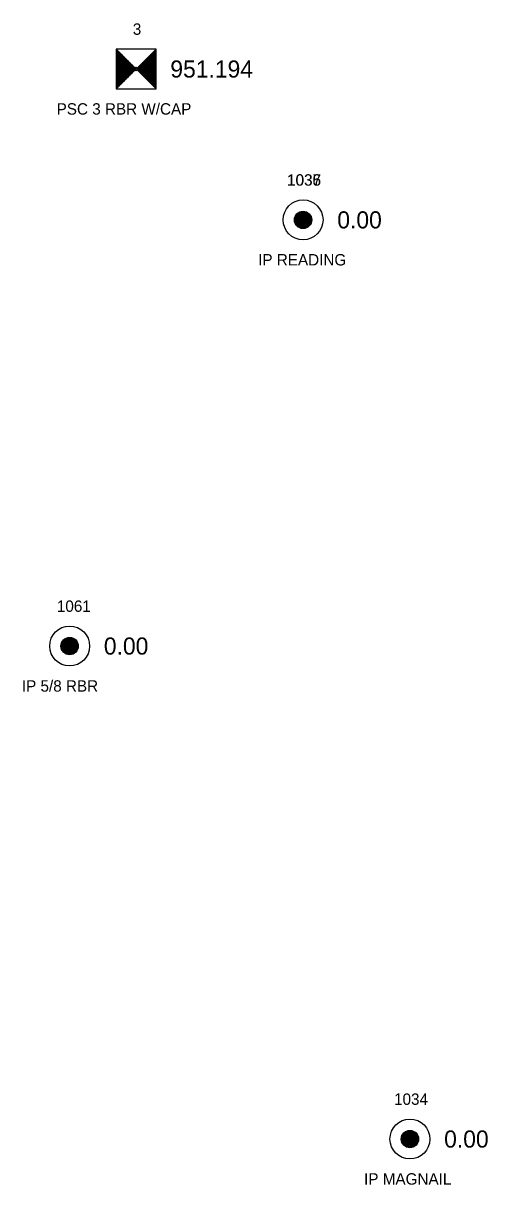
# Model space of a CAD drawing. Extents: x 1528109 to 1531398, y 1157799 to 1162548.
# Drawn here: x 1529035.6 to 1529076.3, y 1162446.1 to 1162548 of the extents above; entities that cross this region are included whole.
import ezdxf

# ---------------------------------------------------------------- set-up
doc = ezdxf.new("R2010")
doc.units = 0
for name, color, linetype in [('RD_EX_DV_Prop_txCode', 7, 'Continuous'), ('RD_EX_DV_PropPin', 7, 'Continuous'), ('RD_EX_TX_DV_Prop_ELEV', 7, 'Continuous'), ('RD_HC_Survey', 7, 'Continuous'), ('RD_HC_Survey_ELEV', 7, 'Continuous'), ('RD_HC_txCode', 7, 'Continuous'), ('RD_SMD_Locator', 7, 'Continuous')]:
    doc.layers.add(name, color=color, linetype=linetype)

msp = doc.modelspace()

# ---------------------------------------------------------------- linework, layer by layer
at = {"layer": 'RD_EX_DV_PropPin'}
for p, q in [((1529059.6, 1162530.18), (1529059.6, 1162531.28)), ((1529059.6, 1162530.18), (1529059.6, 1162531.28)), ((1529059.6, 1162530.18), (1529059.6, 1162531.28)), ((1529059.64, 1162530.14), (1529059.64, 1162531.31)), ((1529059.64, 1162530.14), (1529059.64, 1162531.31)), ((1529059.64, 1162530.14), (1529059.64, 1162531.31)), ((1529059.67, 1162530.12), (1529059.67, 1162531.34)), ((1529059.67, 1162530.12), (1529059.67, 1162531.34)), ((1529059.67, 1162530.12), (1529059.67, 1162531.34)), ((1529059.71, 1162530.09), (1529059.71, 1162531.36)), ((1529059.71, 1162530.09), (1529059.71, 1162531.36)), ((1529059.71, 1162530.09), (1529059.71, 1162531.36)), ((1529059.74, 1162530.07), (1529059.74, 1162531.38)), ((1529059.74, 1162530.07), (1529059.74, 1162531.38)), ((1529059.74, 1162530.07), (1529059.74, 1162531.38)), ((1529059.78, 1162530.05), (1529059.78, 1162531.4)), ((1529059.78, 1162530.05), (1529059.78, 1162531.4)), ((1529059.78, 1162530.05), (1529059.78, 1162531.4)), ((1529059.81, 1162530.03), (1529059.81, 1162531.42)), ((1529059.81, 1162530.03), (1529059.81, 1162531.42)), ((1529059.81, 1162530.03), (1529059.81, 1162531.42)), ((1529059.85, 1162530.02), (1529059.85, 1162531.43)), ((1529059.85, 1162530.02), (1529059.85, 1162531.43)), ((1529059.85, 1162530.02), (1529059.85, 1162531.43)), ((1529059.88, 1162530.01), (1529059.88, 1162531.45)), ((1529059.88, 1162530.01), (1529059.88, 1162531.45)), ((1529059.88, 1162530.01), (1529059.88, 1162531.45)), ((1529059.92, 1162529.99), (1529059.92, 1162531.46)), ((1529059.92, 1162529.99), (1529059.92, 1162531.46)), ((1529059.92, 1162529.99), (1529059.92, 1162531.46)), ((1529059.95, 1162529.99), (1529059.95, 1162531.47)), ((1529059.95, 1162529.99), (1529059.95, 1162531.47)), ((1529059.95, 1162529.99), (1529059.95, 1162531.47)), ((1529059.99, 1162529.98), (1529059.99, 1162531.47)), ((1529059.99, 1162529.98), (1529059.99, 1162531.47)), ((1529059.99, 1162529.98), (1529059.99, 1162531.47)), ((1529060.02, 1162529.97), (1529060.02, 1162531.48)), ((1529060.02, 1162529.97), (1529060.02, 1162531.48)), ((1529060.02, 1162529.97), (1529060.02, 1162531.48)), ((1529060.06, 1162529.97), (1529060.06, 1162531.48)), ((1529060.06, 1162529.97), (1529060.06, 1162531.48)), ((1529060.06, 1162529.97), (1529060.06, 1162531.48)), ((1529060.09, 1162529.97), (1529060.09, 1162531.49)), ((1529060.09, 1162529.97), (1529060.09, 1162531.49)), ((1529060.09, 1162529.97), (1529060.09, 1162531.49)), ((1529060.13, 1162529.97), (1529060.13, 1162531.49)), ((1529060.13, 1162529.97), (1529060.13, 1162531.49)), ((1529060.13, 1162529.97), (1529060.13, 1162531.49)), ((1529060.16, 1162529.97), (1529060.16, 1162531.49)), ((1529060.16, 1162529.97), (1529060.16, 1162531.49)), ((1529060.16, 1162529.97), (1529060.16, 1162531.49)), ((1529060.2, 1162529.97), (1529060.2, 1162531.48)), ((1529060.2, 1162529.97), (1529060.2, 1162531.48)), ((1529060.2, 1162529.97), (1529060.2, 1162531.48)), ((1529060.23, 1162529.97), (1529060.23, 1162531.48)), ((1529060.23, 1162529.97), (1529060.23, 1162531.48)), ((1529060.23, 1162529.97), (1529060.23, 1162531.48)), ((1529060.27, 1162529.98), (1529060.27, 1162531.47)), ((1529060.27, 1162529.98), (1529060.27, 1162531.47)), ((1529060.27, 1162529.98), (1529060.27, 1162531.47)), ((1529060.3, 1162529.99), (1529060.3, 1162531.47)), ((1529060.3, 1162529.99), (1529060.3, 1162531.47)), ((1529060.3, 1162529.99), (1529060.3, 1162531.47)), ((1529060.34, 1162529.99), (1529060.34, 1162531.46)), ((1529060.34, 1162529.99), (1529060.34, 1162531.46)), ((1529060.34, 1162529.99), (1529060.34, 1162531.46)), ((1529060.37, 1162530.01), (1529060.37, 1162531.45)), ((1529060.37, 1162530.01), (1529060.37, 1162531.45)), ((1529060.37, 1162530.01), (1529060.37, 1162531.45)), ((1529060.41, 1162530.02), (1529060.41, 1162531.43)), ((1529060.41, 1162530.02), (1529060.41, 1162531.43)), ((1529060.41, 1162530.02), (1529060.41, 1162531.43)), ((1529060.44, 1162530.03), (1529060.44, 1162531.42)), ((1529060.44, 1162530.03), (1529060.44, 1162531.42)), ((1529060.44, 1162530.03), (1529060.44, 1162531.42)), ((1529060.48, 1162530.05), (1529060.48, 1162531.4)), ((1529060.48, 1162530.05), (1529060.48, 1162531.4)), ((1529060.48, 1162530.05), (1529060.48, 1162531.4)), ((1529060.51, 1162530.07), (1529060.51, 1162531.38)), ((1529060.51, 1162530.07), (1529060.51, 1162531.38)), ((1529060.51, 1162530.07), (1529060.51, 1162531.38)), ((1529060.55, 1162530.09), (1529060.55, 1162531.36)), ((1529060.55, 1162530.09), (1529060.55, 1162531.36)), ((1529060.55, 1162530.09), (1529060.55, 1162531.36)), ((1529060.58, 1162530.12), (1529060.58, 1162531.34)), ((1529060.58, 1162530.12), (1529060.58, 1162531.34)), ((1529060.58, 1162530.12), (1529060.58, 1162531.34)), ((1529060.62, 1162530.14), (1529060.62, 1162531.31)), ((1529060.62, 1162530.14), (1529060.62, 1162531.31)), ((1529060.62, 1162530.14), (1529060.62, 1162531.31)), ((1529060.65, 1162530.18), (1529060.65, 1162531.28)), ((1529060.65, 1162530.18), (1529060.65, 1162531.28)), ((1529060.65, 1162530.18), (1529060.65, 1162531.28)), ((1529059.39, 1162530.53), (1529059.39, 1162530.92)), ((1529059.39, 1162530.53), (1529059.39, 1162530.92)), ((1529059.39, 1162530.53), (1529059.39, 1162530.92)), ((1529059.43, 1162530.43), (1529059.43, 1162531.02)), ((1529059.43, 1162530.43), (1529059.43, 1162531.02)), ((1529059.43, 1162530.43), (1529059.43, 1162531.02)), ((1529059.46, 1162530.36), (1529059.46, 1162531.1)), ((1529059.46, 1162530.36), (1529059.46, 1162531.1)), ((1529059.46, 1162530.36), (1529059.46, 1162531.1)), ((1529059.5, 1162530.3), (1529059.5, 1162531.15)), ((1529059.5, 1162530.3), (1529059.5, 1162531.15)), ((1529059.5, 1162530.3), (1529059.5, 1162531.15)), ((1529059.53, 1162530.25), (1529059.53, 1162531.2)), ((1529059.53, 1162530.25), (1529059.53, 1162531.2)), ((1529059.53, 1162530.25), (1529059.53, 1162531.2)), ((1529059.57, 1162530.21), (1529059.57, 1162531.24)), ((1529059.57, 1162530.21), (1529059.57, 1162531.24)), ((1529059.57, 1162530.21), (1529059.57, 1162531.24)), ((1529060.69, 1162530.21), (1529060.69, 1162531.24)), ((1529060.69, 1162530.21), (1529060.69, 1162531.24)), ((1529060.69, 1162530.21), (1529060.69, 1162531.24)), ((1529060.72, 1162530.25), (1529060.72, 1162531.2)), ((1529060.72, 1162530.25), (1529060.72, 1162531.2)), ((1529060.72, 1162530.25), (1529060.72, 1162531.2)), ((1529060.76, 1162530.3), (1529060.76, 1162531.15)), ((1529060.76, 1162530.3), (1529060.76, 1162531.15)), ((1529060.76, 1162530.3), (1529060.76, 1162531.15)), ((1529060.79, 1162530.36), (1529060.79, 1162531.1)), ((1529060.79, 1162530.36), (1529060.79, 1162531.1)), ((1529060.79, 1162530.36), (1529060.79, 1162531.1)), ((1529060.83, 1162530.43), (1529060.83, 1162531.02)), ((1529060.83, 1162530.43), (1529060.83, 1162531.02)), ((1529060.83, 1162530.43), (1529060.83, 1162531.02)), ((1529060.86, 1162530.53), (1529060.86, 1162530.92)), ((1529060.86, 1162530.53), (1529060.86, 1162530.92)), ((1529060.86, 1162530.53), (1529060.86, 1162530.92)), ((1529038.96, 1162493.05), (1529038.96, 1162493.65)), ((1529039, 1162492.98), (1529039, 1162493.72)), ((1529039.03, 1162492.93), (1529039.03, 1162493.78)), ((1529039.07, 1162492.88), (1529039.07, 1162493.83)), ((1529039.1, 1162492.84), (1529039.1, 1162493.87)), ((1529039.14, 1162492.8), (1529039.14, 1162493.9)), ((1529039.17, 1162492.77), (1529039.17, 1162493.93)), ((1529039.21, 1162492.74), (1529039.21, 1162493.96)), ((1529039.24, 1162492.72), (1529039.24, 1162493.99)), ((1529039.28, 1162492.7), (1529039.28, 1162494.01)), ((1529039.31, 1162492.68), (1529039.31, 1162494.03)), ((1529039.35, 1162492.66), (1529039.35, 1162494.05)), ((1529039.38, 1162492.65), (1529039.38, 1162494.06)), ((1529039.42, 1162492.63), (1529039.42, 1162494.07)), ((1529039.45, 1162492.62), (1529039.45, 1162494.08)), ((1529039.49, 1162492.61), (1529039.49, 1162494.09)), ((1529039.52, 1162492.6), (1529039.52, 1162494.1)), ((1529039.56, 1162492.6), (1529039.56, 1162494.11)), ((1529039.59, 1162492.59), (1529039.59, 1162494.11)), ((1529039.63, 1162492.59), (1529039.63, 1162494.11)), ((1529039.66, 1162492.59), (1529039.66, 1162494.11)), ((1529039.7, 1162492.59), (1529039.7, 1162494.11)), ((1529039.73, 1162492.59), (1529039.73, 1162494.11)), ((1529039.77, 1162492.6), (1529039.77, 1162494.11)), ((1529039.8, 1162492.6), (1529039.8, 1162494.1)), ((1529039.84, 1162492.61), (1529039.84, 1162494.09)), ((1529039.87, 1162492.62), (1529039.87, 1162494.08)), ((1529039.91, 1162492.63), (1529039.91, 1162494.07)), ((1529039.94, 1162492.65), (1529039.94, 1162494.06)), ((1529039.98, 1162492.66), (1529039.98, 1162494.05)), ((1529040.01, 1162492.68), (1529040.01, 1162494.03)), ((1529040.05, 1162492.7), (1529040.05, 1162494.01)), ((1529040.08, 1162492.72), (1529040.08, 1162493.99)), ((1529040.12, 1162492.74), (1529040.12, 1162493.96)), ((1529040.15, 1162492.77), (1529040.15, 1162493.93)), ((1529040.19, 1162492.8), (1529040.19, 1162493.9)), ((1529040.22, 1162492.84), (1529040.22, 1162493.87)), ((1529040.26, 1162492.88), (1529040.26, 1162493.83)), ((1529040.29, 1162492.93), (1529040.29, 1162493.78)), ((1529040.33, 1162492.98), (1529040.33, 1162493.72)), ((1529040.36, 1162493.05), (1529040.36, 1162493.65)), ((1529038.93, 1162493.16), (1529038.93, 1162493.55)), ((1529040.4, 1162493.16), (1529040.4, 1162493.55)), ((1529069.15, 1162449.44), (1529069.15, 1162450.79)), ((1529069.18, 1162449.42), (1529069.18, 1162450.81)), ((1529069.22, 1162449.41), (1529069.22, 1162450.82)), ((1529069.25, 1162449.39), (1529069.25, 1162450.83)), ((1529069.29, 1162449.38), (1529069.29, 1162450.84)), ((1529069.32, 1162449.37), (1529069.32, 1162450.85)), ((1529069.36, 1162449.37), (1529069.36, 1162450.86)), ((1529069.39, 1162449.36), (1529069.39, 1162450.87)), ((1529069.43, 1162449.36), (1529069.43, 1162450.87)), ((1529069.46, 1162449.35), (1529069.46, 1162450.87)), ((1529069.5, 1162449.35), (1529069.5, 1162450.87)), ((1529069.53, 1162449.35), (1529069.53, 1162450.87)), ((1529069.57, 1162449.36), (1529069.57, 1162450.87)), ((1529069.61, 1162449.36), (1529069.61, 1162450.87)), ((1529069.64, 1162449.37), (1529069.64, 1162450.86)), ((1529069.68, 1162449.37), (1529069.68, 1162450.85)), ((1529069.71, 1162449.38), (1529069.71, 1162450.84)), ((1529069.75, 1162449.39), (1529069.75, 1162450.83)), ((1529069.78, 1162449.41), (1529069.78, 1162450.82)), ((1529069.82, 1162449.42), (1529069.82, 1162450.81)), ((1529069.85, 1162449.44), (1529069.85, 1162450.79)), ((1529068.76, 1162449.92), (1529068.76, 1162450.31)), ((1529068.8, 1162449.82), (1529068.8, 1162450.41)), ((1529068.83, 1162449.74), (1529068.83, 1162450.48)), ((1529068.87, 1162449.69), (1529068.87, 1162450.54)), ((1529068.9, 1162449.64), (1529068.9, 1162450.59)), ((1529068.94, 1162449.6), (1529068.94, 1162450.63)), ((1529068.97, 1162449.56), (1529068.97, 1162450.66)), ((1529069.01, 1162449.53), (1529069.01, 1162450.7)), ((1529069.04, 1162449.5), (1529069.04, 1162450.72)), ((1529069.08, 1162449.48), (1529069.08, 1162450.75)), ((1529069.11, 1162449.46), (1529069.11, 1162450.77)), ((1529069.89, 1162449.46), (1529069.89, 1162450.77)), ((1529069.92, 1162449.48), (1529069.92, 1162450.75)), ((1529069.96, 1162449.5), (1529069.96, 1162450.72)), ((1529069.99, 1162449.53), (1529069.99, 1162450.7)), ((1529070.03, 1162449.56), (1529070.03, 1162450.66)), ((1529070.06, 1162449.6), (1529070.06, 1162450.63)), ((1529070.1, 1162449.64), (1529070.1, 1162450.59)), ((1529070.13, 1162449.69), (1529070.13, 1162450.54)), ((1529070.17, 1162449.74), (1529070.17, 1162450.48)), ((1529070.2, 1162449.82), (1529070.2, 1162450.41)), ((1529070.24, 1162449.92), (1529070.24, 1162450.31))]:
    msp.add_line(p, q, dxfattribs=at)
for centre, radius in [((1529060.13, 1162530.73), 1.75), ((1529060.13, 1162530.73), 1.75), ((1529060.13, 1162530.73), 1.75), ((1529060.13, 1162530.73), 0.761), ((1529060.13, 1162530.73), 0.761), ((1529060.13, 1162530.73), 0.761), ((1529039.66, 1162493.35), 1.75), ((1529039.66, 1162493.35), 0.761), ((1529069.5, 1162450.11), 1.75), ((1529069.5, 1162450.11), 0.761)]:
    msp.add_circle(centre, radius, dxfattribs=at)
at = {"layer": 'RD_HC_Survey'}
for p, q in [((1529043.74, 1162545.71), (1529047.24, 1162542.21)), ((1529047.24, 1162545.71), (1529043.74, 1162542.21)), ((1529043.76, 1162545.69), (1529043.76, 1162542.24)), ((1529043.79, 1162545.66), (1529043.79, 1162542.26)), ((1529043.81, 1162545.64), (1529043.81, 1162542.29)), ((1529043.84, 1162545.61), (1529043.84, 1162542.31)), ((1529043.86, 1162545.59), (1529043.86, 1162542.34)), ((1529043.88, 1162545.56), (1529043.88, 1162542.36)), ((1529043.91, 1162545.54), (1529043.91, 1162542.38)), ((1529047.06, 1162545.54), (1529047.06, 1162542.38)), ((1529047.09, 1162545.56), (1529047.09, 1162542.36)), ((1529047.11, 1162545.59), (1529047.11, 1162542.34)), ((1529047.14, 1162545.61), (1529047.14, 1162542.31)), ((1529047.16, 1162545.64), (1529047.16, 1162542.29)), ((1529047.19, 1162545.66), (1529047.19, 1162542.26)), ((1529047.21, 1162545.69), (1529047.21, 1162542.24)), ((1529043.93, 1162545.51), (1529043.93, 1162542.41)), ((1529043.96, 1162545.49), (1529043.96, 1162542.43)), ((1529043.98, 1162545.46), (1529043.98, 1162542.46)), ((1529044.01, 1162545.44), (1529044.01, 1162542.48)), ((1529044.03, 1162545.41), (1529044.03, 1162542.51)), ((1529044.06, 1162545.39), (1529044.06, 1162542.53)), ((1529044.08, 1162545.37), (1529044.08, 1162542.56)), ((1529044.11, 1162545.34), (1529044.11, 1162542.58)), ((1529044.13, 1162545.32), (1529044.13, 1162542.61)), ((1529044.16, 1162545.29), (1529044.16, 1162542.63)), ((1529044.18, 1162545.27), (1529044.18, 1162542.66)), ((1529044.21, 1162545.24), (1529044.21, 1162542.68)), ((1529044.23, 1162545.22), (1529044.23, 1162542.71)), ((1529044.26, 1162545.19), (1529044.26, 1162542.73)), ((1529044.28, 1162545.17), (1529044.28, 1162542.76)), ((1529044.31, 1162545.14), (1529044.31, 1162542.78)), ((1529044.33, 1162545.12), (1529044.33, 1162542.81)), ((1529044.35, 1162545.09), (1529044.35, 1162542.83)), ((1529044.38, 1162545.07), (1529044.38, 1162542.85)), ((1529044.4, 1162545.04), (1529044.4, 1162542.88)), ((1529044.43, 1162545.02), (1529044.43, 1162542.9)), ((1529044.45, 1162544.99), (1529044.45, 1162542.93)), ((1529044.48, 1162544.97), (1529044.48, 1162542.95)), ((1529044.5, 1162544.94), (1529044.5, 1162542.98)), ((1529044.53, 1162544.92), (1529044.53, 1162543)), ((1529044.55, 1162544.89), (1529044.55, 1162543.03)), ((1529044.58, 1162544.87), (1529044.58, 1162543.05)), ((1529044.6, 1162544.85), (1529044.6, 1162543.08)), ((1529044.63, 1162544.82), (1529044.63, 1162543.1)), ((1529044.65, 1162544.8), (1529044.65, 1162543.13)), ((1529044.68, 1162544.77), (1529044.68, 1162543.15)), ((1529044.7, 1162544.75), (1529044.7, 1162543.18)), ((1529044.73, 1162544.72), (1529044.73, 1162543.2)), ((1529044.75, 1162544.7), (1529044.75, 1162543.23)), ((1529044.78, 1162544.67), (1529044.78, 1162543.25)), ((1529044.8, 1162544.65), (1529044.8, 1162543.28)), ((1529044.82, 1162544.62), (1529044.82, 1162543.3)), ((1529044.85, 1162544.6), (1529044.85, 1162543.33)), ((1529044.87, 1162544.57), (1529044.87, 1162543.35)), ((1529044.9, 1162544.55), (1529044.9, 1162543.37)), ((1529044.92, 1162544.52), (1529044.92, 1162543.4)), ((1529046.05, 1162544.52), (1529046.05, 1162543.4)), ((1529046.07, 1162544.55), (1529046.07, 1162543.37)), ((1529046.1, 1162544.57), (1529046.1, 1162543.35)), ((1529046.12, 1162544.6), (1529046.12, 1162543.33)), ((1529046.15, 1162544.62), (1529046.15, 1162543.3)), ((1529046.17, 1162544.65), (1529046.17, 1162543.28)), ((1529046.2, 1162544.67), (1529046.2, 1162543.25)), ((1529046.22, 1162544.7), (1529046.22, 1162543.23)), ((1529046.25, 1162544.72), (1529046.25, 1162543.2)), ((1529046.27, 1162544.75), (1529046.27, 1162543.18)), ((1529046.3, 1162544.77), (1529046.3, 1162543.15)), ((1529046.32, 1162544.8), (1529046.32, 1162543.13)), ((1529046.35, 1162544.82), (1529046.35, 1162543.1)), ((1529046.37, 1162544.85), (1529046.37, 1162543.08)), ((1529046.39, 1162544.87), (1529046.39, 1162543.05)), ((1529046.42, 1162544.89), (1529046.42, 1162543.03)), ((1529046.44, 1162544.92), (1529046.44, 1162543)), ((1529046.47, 1162544.94), (1529046.47, 1162542.98)), ((1529046.49, 1162544.97), (1529046.49, 1162542.95)), ((1529046.52, 1162544.99), (1529046.52, 1162542.93)), ((1529046.54, 1162545.02), (1529046.54, 1162542.9)), ((1529046.57, 1162545.04), (1529046.57, 1162542.88)), ((1529046.59, 1162545.07), (1529046.59, 1162542.85)), ((1529046.62, 1162545.09), (1529046.62, 1162542.83)), ((1529046.64, 1162545.12), (1529046.64, 1162542.81)), ((1529046.67, 1162545.14), (1529046.67, 1162542.78)), ((1529046.69, 1162545.17), (1529046.69, 1162542.76)), ((1529046.72, 1162545.19), (1529046.72, 1162542.73)), ((1529046.74, 1162545.22), (1529046.74, 1162542.71)), ((1529046.77, 1162545.24), (1529046.77, 1162542.68)), ((1529046.79, 1162545.27), (1529046.79, 1162542.66)), ((1529046.82, 1162545.29), (1529046.82, 1162542.63)), ((1529046.84, 1162545.32), (1529046.84, 1162542.61)), ((1529046.86, 1162545.34), (1529046.86, 1162542.58)), ((1529046.89, 1162545.37), (1529046.89, 1162542.56)), ((1529046.91, 1162545.39), (1529046.91, 1162542.53)), ((1529046.94, 1162545.41), (1529046.94, 1162542.51)), ((1529046.96, 1162545.44), (1529046.96, 1162542.48)), ((1529046.99, 1162545.46), (1529046.99, 1162542.46)), ((1529047.01, 1162545.49), (1529047.01, 1162542.43)), ((1529047.04, 1162545.51), (1529047.04, 1162542.41)), ((1529044.95, 1162544.5), (1529044.95, 1162543.42)), ((1529044.97, 1162544.47), (1529044.97, 1162543.45)), ((1529045, 1162544.45), (1529045, 1162543.47)), ((1529045.02, 1162544.42), (1529045.02, 1162543.5)), ((1529045.05, 1162544.4), (1529045.05, 1162543.52)), ((1529045.07, 1162544.38), (1529045.07, 1162543.55)), ((1529045.1, 1162544.35), (1529045.1, 1162543.57)), ((1529045.12, 1162544.33), (1529045.12, 1162543.6)), ((1529045.15, 1162544.3), (1529045.15, 1162543.62)), ((1529045.17, 1162544.28), (1529045.17, 1162543.65)), ((1529045.2, 1162544.25), (1529045.2, 1162543.67)), ((1529045.22, 1162544.23), (1529045.22, 1162543.7)), ((1529045.25, 1162544.2), (1529045.25, 1162543.72)), ((1529045.27, 1162544.18), (1529045.27, 1162543.75)), ((1529045.3, 1162544.15), (1529045.3, 1162543.77)), ((1529045.32, 1162544.13), (1529045.32, 1162543.8)), ((1529045.34, 1162544.1), (1529045.34, 1162543.82)), ((1529045.37, 1162544.08), (1529045.37, 1162543.84)), ((1529045.39, 1162544.05), (1529045.39, 1162543.87)), ((1529045.42, 1162544.03), (1529045.42, 1162543.89)), ((1529045.44, 1162544), (1529045.44, 1162543.92)), ((1529045.47, 1162543.98), (1529045.47, 1162543.94)), ((1529045.5, 1162543.98), (1529045.5, 1162543.94)), ((1529045.53, 1162544), (1529045.53, 1162543.92)), ((1529045.55, 1162544.03), (1529045.55, 1162543.89)), ((1529045.58, 1162544.05), (1529045.58, 1162543.87)), ((1529045.6, 1162544.08), (1529045.6, 1162543.84)), ((1529045.63, 1162544.1), (1529045.63, 1162543.82)), ((1529045.65, 1162544.13), (1529045.65, 1162543.8)), ((1529045.68, 1162544.15), (1529045.68, 1162543.77)), ((1529045.7, 1162544.18), (1529045.7, 1162543.75)), ((1529045.73, 1162544.2), (1529045.73, 1162543.72)), ((1529045.75, 1162544.23), (1529045.75, 1162543.7)), ((1529045.78, 1162544.25), (1529045.78, 1162543.67)), ((1529045.8, 1162544.28), (1529045.8, 1162543.65)), ((1529045.83, 1162544.3), (1529045.83, 1162543.62)), ((1529045.85, 1162544.33), (1529045.85, 1162543.6)), ((1529045.87, 1162544.35), (1529045.87, 1162543.57)), ((1529045.9, 1162544.38), (1529045.9, 1162543.55)), ((1529045.92, 1162544.4), (1529045.92, 1162543.52)), ((1529045.95, 1162544.42), (1529045.95, 1162543.5)), ((1529045.97, 1162544.45), (1529045.97, 1162543.47)), ((1529046, 1162544.47), (1529046, 1162543.45)), ((1529046.02, 1162544.5), (1529046.02, 1162543.42))]:
    msp.add_line(p, q, dxfattribs=at)
msp.add_lwpolyline([(1529047.24, 1162545.71), (1529043.74, 1162545.71), (1529043.74, 1162542.21), (1529047.24, 1162542.21)], close=True, dxfattribs=at)
at = {"layer": 'RD_SMD_Locator'}
for centre in [(1529045.49, 1162543.96), (1529060.13, 1162530.73), (1529060.13, 1162530.73), (1529060.13, 1162530.73), (1529039.66, 1162493.35), (1529069.5, 1162450.11)]:
    msp.add_circle(centre, 0.15, dxfattribs=at)

# ---------------------------------------------------------------- texts
at = {"layer": 'RD_EX_DV_Prop_txCode'}
for s, p in [('1036', (1529058.72, 1162533.73)), ('1035', (1529058.74, 1162533.73)), ('1037', (1529058.74, 1162533.73)), ('IP READING', (1529056.19, 1162526.73)), ('IP READING', (1529056.19, 1162526.73)), ('IP READING', (1529056.19, 1162526.73)), ('1061', (1529038.54, 1162496.35)), ('IP 5/8 RBR', (1529035.47, 1162489.35)), ('1034', (1529068.11, 1162453.11)), ('IP MAGNAIL', (1529065.48, 1162446.11))]:
    msp.add_text(s, height=1, dxfattribs=at).set_placement(p)
at = {"layer": 'RD_EX_TX_DV_Prop_ELEV'}
for p in [(1529063.13, 1162529.98), (1529063.13, 1162529.98), (1529063.13, 1162529.98), (1529042.66, 1162492.6), (1529072.5, 1162449.36)]:
    msp.add_text('0.00', height=1.5, dxfattribs=at).set_placement(p)
at = {"layer": 'RD_HC_Survey_ELEV'}
msp.add_text('951.194', height=1.5, dxfattribs=at).set_placement((1529048.49, 1162543.21))
at = {"layer": 'RD_HC_txCode'}
for s, p in [('3', (1529045.2, 1162546.96)), ('PSC 3 RBR W/CAP', (1529038.52, 1162539.96))]:
    msp.add_text(s, height=1, dxfattribs=at).set_placement(p)

doc.saveas('drawing.dxf')
